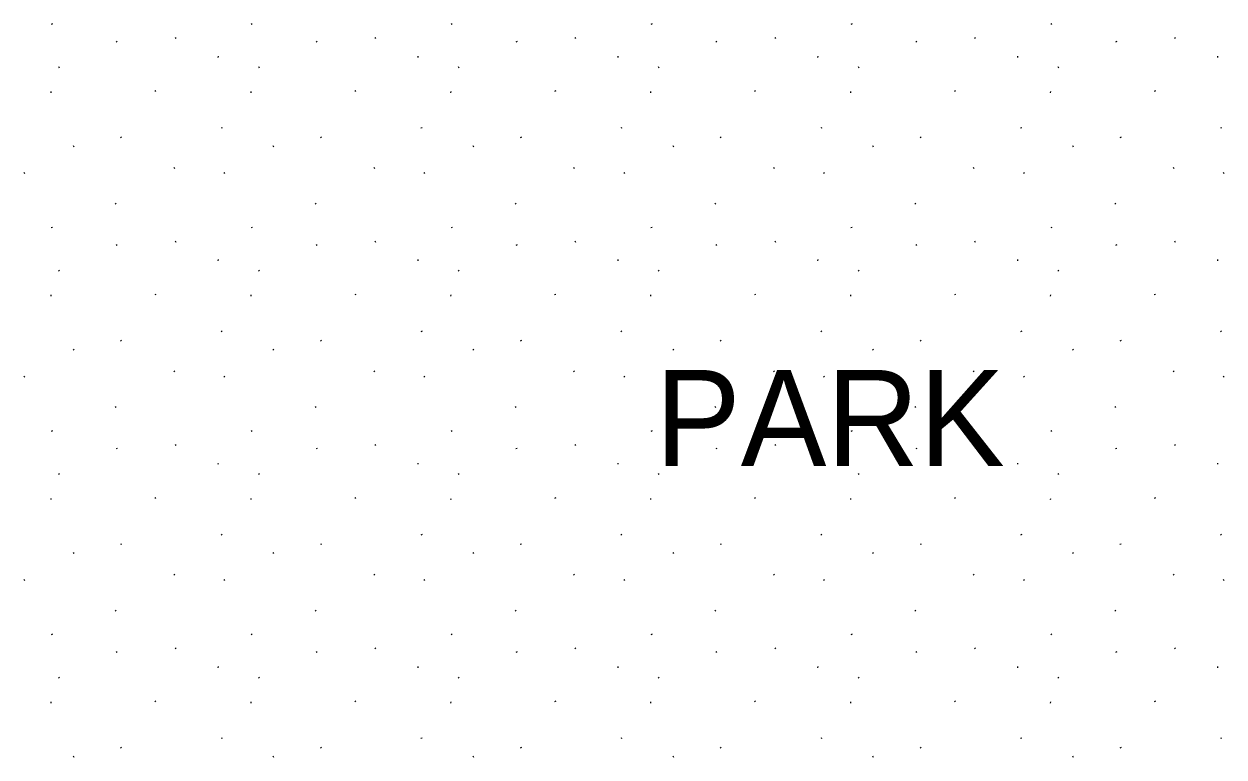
# Model space of a CAD drawing. Extents: x 419396 to 421519, y 4453567 to 4456767.
# Drawn here: x 420346 to 420396, y 4454755.4 to 4454786 of the extents above; entities that cross this region are included whole.
import ezdxf

# ---------------------------------------------------------------- set-up
doc = ezdxf.new("R2010")
doc.units = 0
doc.layers.add('Level 41', color=7, linetype='Continuous')
doc.layers.add('LEVEL61', color=7, linetype='Continuous')

msp = doc.modelspace()

# ---------------------------------------------------------------- linework, layer by layer
at = {"layer": 'Level 41'}
for p, q in [((420347.213, 4454785.976), (420347.166, 4454785.953)), ((420355.545, 4454785.976), (420355.499, 4454785.953)), ((420363.878, 4454785.976), (420363.831, 4454785.953)), ((420372.21, 4454785.976), (420372.163, 4454785.953)), ((420380.542, 4454785.976), (420380.495, 4454785.953)), ((420388.874, 4454785.976), (420388.827, 4454785.953)), ((420352.325, 4454785.411), (420352.353, 4454785.367)), ((420360.657, 4454785.411), (420360.685, 4454785.367)), ((420368.989, 4454785.411), (420369.017, 4454785.367)), ((420377.321, 4454785.411), (420377.349, 4454785.367)), ((420385.654, 4454785.411), (420385.682, 4454785.367)), ((420393.986, 4454785.411), (420394.014, 4454785.367)), ((420349.916, 4454785.247), (420349.869, 4454785.224)), ((420358.248, 4454785.247), (420358.202, 4454785.224)), ((420366.581, 4454785.247), (420366.534, 4454785.224)), ((420374.913, 4454785.247), (420374.866, 4454785.224)), ((420383.245, 4454785.247), (420383.198, 4454785.224)), ((420391.577, 4454785.247), (420391.53, 4454785.224)), ((420354.124, 4454784.582), (420354.132, 4454784.633)), ((420362.457, 4454784.582), (420362.464, 4454784.633)), ((420370.789, 4454784.582), (420370.796, 4454784.633)), ((420379.121, 4454784.582), (420379.128, 4454784.633)), ((420387.453, 4454784.582), (420387.461, 4454784.633)), ((420395.785, 4454784.582), (420395.793, 4454784.633)), ((420347.466, 4454784.196), (420347.494, 4454784.152)), ((420355.798, 4454784.196), (420355.826, 4454784.152)), ((420364.13, 4454784.196), (420364.158, 4454784.152)), ((420372.462, 4454784.196), (420372.49, 4454784.152)), ((420380.794, 4454784.196), (420380.822, 4454784.152)), ((420389.127, 4454784.196), (420389.155, 4454784.152)), ((420347.159, 4454783.108), (420347.166, 4454783.159)), ((420351.526, 4454783.182), (420351.479, 4454783.159)), ((420355.491, 4454783.108), (420355.499, 4454783.159)), ((420359.858, 4454783.182), (420359.811, 4454783.159)), ((420363.823, 4454783.108), (420363.831, 4454783.159)), ((420368.19, 4454783.182), (420368.143, 4454783.159)), ((420372.155, 4454783.108), (420372.163, 4454783.159)), ((420376.522, 4454783.182), (420376.476, 4454783.159)), ((420380.488, 4454783.108), (420380.495, 4454783.159)), ((420384.855, 4454783.182), (420384.808, 4454783.159)), ((420388.82, 4454783.108), (420388.827, 4454783.159)), ((420393.187, 4454783.182), (420393.14, 4454783.159)), ((420354.289, 4454781.648), (420354.243, 4454781.625)), ((420362.622, 4454781.648), (420362.575, 4454781.625)), ((420370.954, 4454781.648), (420370.907, 4454781.625)), ((420379.286, 4454781.648), (420379.239, 4454781.625)), ((420387.618, 4454781.648), (420387.571, 4454781.625)), ((420395.95, 4454781.648), (420395.904, 4454781.625)), ((420348.073, 4454780.9), (420348.101, 4454780.857)), ((420350.098, 4454781.253), (420350.052, 4454781.23)), ((420356.405, 4454780.9), (420356.433, 4454780.857)), ((420358.431, 4454781.253), (420358.384, 4454781.23)), ((420364.737, 4454780.9), (420364.765, 4454780.857)), ((420366.763, 4454781.253), (420366.716, 4454781.23)), ((420373.069, 4454780.9), (420373.098, 4454780.857)), ((420375.095, 4454781.253), (420375.048, 4454781.23)), ((420381.402, 4454780.9), (420381.43, 4454780.857)), ((420383.427, 4454781.253), (420383.38, 4454781.23)), ((420389.734, 4454780.9), (420389.762, 4454780.857)), ((420391.759, 4454781.253), (420391.713, 4454781.23)), ((420352.27, 4454779.997), (420352.298, 4454779.953)), ((420360.603, 4454779.997), (420360.631, 4454779.953)), ((420368.935, 4454779.997), (420368.963, 4454779.953)), ((420377.267, 4454779.997), (420377.295, 4454779.953)), ((420385.599, 4454779.997), (420385.627, 4454779.953)), ((420393.931, 4454779.997), (420393.959, 4454779.953)), ((420346.027, 4454779.777), (420346.055, 4454779.733)), ((420354.359, 4454779.777), (420354.388, 4454779.733)), ((420362.692, 4454779.777), (420362.72, 4454779.733)), ((420371.024, 4454779.777), (420371.052, 4454779.733)), ((420379.356, 4454779.777), (420379.384, 4454779.733)), ((420387.688, 4454779.777), (420387.716, 4454779.733)), ((420396.02, 4454779.777), (420396.049, 4454779.733)), ((420349.834, 4454778.501), (420349.862, 4454778.457)), ((420358.167, 4454778.501), (420358.195, 4454778.457)), ((420366.499, 4454778.501), (420366.527, 4454778.457)), ((420374.831, 4454778.501), (420374.859, 4454778.457)), ((420383.163, 4454778.501), (420383.191, 4454778.457)), ((420391.495, 4454778.501), (420391.523, 4454778.457)), ((420347.213, 4454777.488), (420347.166, 4454777.465)), ((420355.545, 4454777.488), (420355.499, 4454777.465)), ((420363.878, 4454777.488), (420363.831, 4454777.465)), ((420372.21, 4454777.488), (420372.163, 4454777.465)), ((420380.542, 4454777.488), (420380.495, 4454777.465)), ((420388.874, 4454777.488), (420388.827, 4454777.465)), ((420352.325, 4454776.922), (420352.353, 4454776.878)), ((420360.657, 4454776.922), (420360.685, 4454776.878)), ((420368.989, 4454776.922), (420369.017, 4454776.878)), ((420377.321, 4454776.922), (420377.349, 4454776.878)), ((420385.654, 4454776.922), (420385.682, 4454776.878)), ((420393.986, 4454776.922), (420394.014, 4454776.878)), ((420349.916, 4454776.759), (420349.869, 4454776.736)), ((420358.248, 4454776.759), (420358.202, 4454776.736)), ((420366.581, 4454776.759), (420366.534, 4454776.736)), ((420374.913, 4454776.759), (420374.866, 4454776.736)), ((420383.245, 4454776.759), (420383.198, 4454776.736)), ((420391.577, 4454776.759), (420391.53, 4454776.736)), ((420354.124, 4454776.093), (420354.132, 4454776.144)), ((420362.457, 4454776.093), (420362.464, 4454776.144)), ((420370.789, 4454776.093), (420370.796, 4454776.144)), ((420379.121, 4454776.093), (420379.128, 4454776.144)), ((420387.453, 4454776.093), (420387.461, 4454776.144)), ((420395.785, 4454776.093), (420395.793, 4454776.144)), ((420347.466, 4454775.707), (420347.494, 4454775.663)), ((420355.798, 4454775.707), (420355.826, 4454775.663)), ((420364.13, 4454775.707), (420364.158, 4454775.663)), ((420372.462, 4454775.707), (420372.49, 4454775.663)), ((420380.794, 4454775.707), (420380.822, 4454775.663)), ((420389.127, 4454775.707), (420389.155, 4454775.663)), ((420347.159, 4454774.619), (420347.166, 4454774.671)), ((420351.526, 4454774.694), (420351.479, 4454774.671)), ((420355.491, 4454774.619), (420355.499, 4454774.671)), ((420359.858, 4454774.694), (420359.811, 4454774.671)), ((420363.823, 4454774.619), (420363.831, 4454774.671)), ((420368.19, 4454774.694), (420368.143, 4454774.671)), ((420372.155, 4454774.619), (420372.163, 4454774.671)), ((420376.522, 4454774.694), (420376.476, 4454774.671)), ((420380.488, 4454774.619), (420380.495, 4454774.671)), ((420384.855, 4454774.694), (420384.808, 4454774.671)), ((420388.82, 4454774.619), (420388.827, 4454774.671)), ((420393.187, 4454774.694), (420393.14, 4454774.671)), ((420354.289, 4454773.159), (420354.243, 4454773.137)), ((420362.622, 4454773.159), (420362.575, 4454773.137)), ((420370.954, 4454773.159), (420370.907, 4454773.137)), ((420379.286, 4454773.159), (420379.239, 4454773.137)), ((420387.618, 4454773.159), (420387.571, 4454773.137)), ((420395.95, 4454773.159), (420395.904, 4454773.137)), ((420348.073, 4454772.412), (420348.101, 4454772.368)), ((420350.098, 4454772.764), (420350.052, 4454772.742)), ((420356.405, 4454772.412), (420356.433, 4454772.368)), ((420358.431, 4454772.764), (420358.384, 4454772.742)), ((420364.737, 4454772.412), (420364.765, 4454772.368)), ((420366.763, 4454772.764), (420366.716, 4454772.742)), ((420373.069, 4454772.412), (420373.098, 4454772.368)), ((420375.095, 4454772.764), (420375.048, 4454772.742)), ((420381.402, 4454772.412), (420381.43, 4454772.368)), ((420383.427, 4454772.764), (420383.38, 4454772.742)), ((420389.734, 4454772.412), (420389.762, 4454772.368)), ((420391.759, 4454772.764), (420391.713, 4454772.742)), ((420352.27, 4454771.508), (420352.298, 4454771.465)), ((420360.603, 4454771.508), (420360.631, 4454771.465)), ((420368.935, 4454771.508), (420368.963, 4454771.465)), ((420377.267, 4454771.508), (420377.295, 4454771.465)), ((420385.599, 4454771.508), (420385.627, 4454771.465)), ((420393.931, 4454771.508), (420393.959, 4454771.465)), ((420346.027, 4454771.288), (420346.055, 4454771.244)), ((420354.359, 4454771.288), (420354.388, 4454771.244)), ((420362.692, 4454771.288), (420362.72, 4454771.244)), ((420371.024, 4454771.288), (420371.052, 4454771.244)), ((420379.356, 4454771.288), (420379.384, 4454771.244)), ((420387.688, 4454771.288), (420387.716, 4454771.244)), ((420396.02, 4454771.288), (420396.049, 4454771.244)), ((420349.834, 4454770.012), (420349.862, 4454769.969)), ((420358.167, 4454770.012), (420358.195, 4454769.969)), ((420366.499, 4454770.012), (420366.527, 4454769.969)), ((420374.831, 4454770.012), (420374.859, 4454769.969)), ((420383.163, 4454770.012), (420383.191, 4454769.969)), ((420391.495, 4454770.012), (420391.523, 4454769.969)), ((420347.213, 4454768.999), (420347.166, 4454768.976)), ((420355.545, 4454768.999), (420355.499, 4454768.976)), ((420363.878, 4454768.999), (420363.831, 4454768.976)), ((420372.21, 4454768.999), (420372.163, 4454768.976)), ((420380.542, 4454768.999), (420380.495, 4454768.976)), ((420388.874, 4454768.999), (420388.827, 4454768.976)), ((420352.325, 4454768.433), (420352.353, 4454768.389)), ((420360.657, 4454768.433), (420360.685, 4454768.389)), ((420368.989, 4454768.433), (420369.017, 4454768.389)), ((420377.321, 4454768.433), (420377.349, 4454768.389)), ((420385.654, 4454768.433), (420385.682, 4454768.389)), ((420393.986, 4454768.433), (420394.014, 4454768.389)), ((420349.916, 4454768.27), (420349.869, 4454768.247)), ((420358.248, 4454768.27), (420358.202, 4454768.247)), ((420366.581, 4454768.27), (420366.534, 4454768.247)), ((420374.913, 4454768.27), (420374.866, 4454768.247)), ((420383.245, 4454768.27), (420383.198, 4454768.247)), ((420391.577, 4454768.27), (420391.53, 4454768.247)), ((420354.124, 4454767.604), (420354.132, 4454767.655)), ((420362.457, 4454767.604), (420362.464, 4454767.655)), ((420370.789, 4454767.604), (420370.796, 4454767.655)), ((420379.121, 4454767.604), (420379.128, 4454767.655)), ((420387.453, 4454767.604), (420387.461, 4454767.655)), ((420395.785, 4454767.604), (420395.793, 4454767.655)), ((420347.466, 4454767.218), (420347.494, 4454767.175)), ((420355.798, 4454767.218), (420355.826, 4454767.175)), ((420364.13, 4454767.218), (420364.158, 4454767.175)), ((420372.462, 4454767.218), (420372.49, 4454767.175)), ((420380.794, 4454767.218), (420380.822, 4454767.175)), ((420389.127, 4454767.218), (420389.155, 4454767.175)), ((420347.159, 4454766.131), (420347.166, 4454766.182)), ((420351.526, 4454766.205), (420351.479, 4454766.182)), ((420355.491, 4454766.131), (420355.499, 4454766.182)), ((420359.858, 4454766.205), (420359.811, 4454766.182)), ((420363.823, 4454766.131), (420363.831, 4454766.182)), ((420368.19, 4454766.205), (420368.143, 4454766.182)), ((420372.155, 4454766.131), (420372.163, 4454766.182)), ((420376.522, 4454766.205), (420376.476, 4454766.182)), ((420380.488, 4454766.131), (420380.495, 4454766.182)), ((420384.855, 4454766.205), (420384.808, 4454766.182)), ((420388.82, 4454766.131), (420388.827, 4454766.182)), ((420393.187, 4454766.205), (420393.14, 4454766.182)), ((420354.289, 4454764.671), (420354.243, 4454764.648)), ((420362.622, 4454764.671), (420362.575, 4454764.648)), ((420370.954, 4454764.671), (420370.907, 4454764.648)), ((420379.286, 4454764.671), (420379.239, 4454764.648)), ((420387.618, 4454764.671), (420387.571, 4454764.648)), ((420395.95, 4454764.671), (420395.904, 4454764.648)), ((420348.073, 4454763.923), (420348.101, 4454763.879)), ((420350.098, 4454764.276), (420350.052, 4454764.253)), ((420356.405, 4454763.923), (420356.433, 4454763.879)), ((420358.431, 4454764.276), (420358.384, 4454764.253)), ((420364.737, 4454763.923), (420364.765, 4454763.879)), ((420366.763, 4454764.276), (420366.716, 4454764.253)), ((420373.069, 4454763.923), (420373.098, 4454763.879)), ((420375.095, 4454764.276), (420375.048, 4454764.253)), ((420381.402, 4454763.923), (420381.43, 4454763.879)), ((420383.427, 4454764.276), (420383.38, 4454764.253)), ((420389.734, 4454763.923), (420389.762, 4454763.879)), ((420391.759, 4454764.276), (420391.713, 4454764.253)), ((420352.27, 4454763.019), (420352.298, 4454762.976)), ((420360.603, 4454763.019), (420360.631, 4454762.976)), ((420368.935, 4454763.019), (420368.963, 4454762.976)), ((420377.267, 4454763.019), (420377.295, 4454762.976)), ((420385.599, 4454763.019), (420385.627, 4454762.976)), ((420393.931, 4454763.019), (420393.959, 4454762.976)), ((420346.027, 4454762.799), (420346.055, 4454762.755)), ((420354.359, 4454762.799), (420354.388, 4454762.755)), ((420362.692, 4454762.799), (420362.72, 4454762.755)), ((420371.024, 4454762.799), (420371.052, 4454762.755)), ((420379.356, 4454762.799), (420379.384, 4454762.755)), ((420387.688, 4454762.799), (420387.716, 4454762.755)), ((420396.02, 4454762.799), (420396.049, 4454762.755)), ((420349.834, 4454761.523), (420349.862, 4454761.48)), ((420358.167, 4454761.523), (420358.195, 4454761.48)), ((420366.499, 4454761.523), (420366.527, 4454761.48)), ((420374.831, 4454761.523), (420374.859, 4454761.48)), ((420383.163, 4454761.523), (420383.191, 4454761.48)), ((420391.495, 4454761.523), (420391.523, 4454761.48)), ((420347.213, 4454760.51), (420347.166, 4454760.487)), ((420355.545, 4454760.51), (420355.499, 4454760.487)), ((420363.878, 4454760.51), (420363.831, 4454760.487)), ((420372.21, 4454760.51), (420372.163, 4454760.487)), ((420380.542, 4454760.51), (420380.495, 4454760.487)), ((420388.874, 4454760.51), (420388.827, 4454760.487)), ((420352.325, 4454759.944), (420352.353, 4454759.901)), ((420360.657, 4454759.944), (420360.685, 4454759.901)), ((420368.989, 4454759.944), (420369.017, 4454759.901)), ((420377.321, 4454759.944), (420377.349, 4454759.901)), ((420385.654, 4454759.944), (420385.682, 4454759.901)), ((420393.986, 4454759.944), (420394.014, 4454759.901)), ((420349.916, 4454759.781), (420349.869, 4454759.758)), ((420358.248, 4454759.781), (420358.202, 4454759.758)), ((420366.581, 4454759.781), (420366.534, 4454759.758)), ((420374.913, 4454759.781), (420374.866, 4454759.758)), ((420383.245, 4454759.781), (420383.198, 4454759.758)), ((420391.577, 4454759.781), (420391.53, 4454759.758)), ((420354.124, 4454759.115), (420354.132, 4454759.166)), ((420362.457, 4454759.115), (420362.464, 4454759.166)), ((420370.789, 4454759.115), (420370.796, 4454759.166)), ((420379.121, 4454759.115), (420379.128, 4454759.166)), ((420387.453, 4454759.115), (420387.461, 4454759.166)), ((420395.785, 4454759.115), (420395.793, 4454759.166)), ((420347.466, 4454758.729), (420347.494, 4454758.686)), ((420355.798, 4454758.729), (420355.826, 4454758.686)), ((420364.13, 4454758.729), (420364.158, 4454758.686)), ((420372.462, 4454758.729), (420372.49, 4454758.686)), ((420380.794, 4454758.729), (420380.822, 4454758.686)), ((420389.127, 4454758.729), (420389.155, 4454758.686)), ((420347.159, 4454757.642), (420347.166, 4454757.693)), ((420351.526, 4454757.716), (420351.479, 4454757.693)), ((420355.491, 4454757.642), (420355.499, 4454757.693)), ((420359.858, 4454757.716), (420359.811, 4454757.693)), ((420363.823, 4454757.642), (420363.831, 4454757.693)), ((420368.19, 4454757.716), (420368.143, 4454757.693)), ((420372.155, 4454757.642), (420372.163, 4454757.693)), ((420376.522, 4454757.716), (420376.476, 4454757.693)), ((420380.488, 4454757.642), (420380.495, 4454757.693)), ((420384.855, 4454757.716), (420384.808, 4454757.693)), ((420388.82, 4454757.642), (420388.827, 4454757.693)), ((420393.187, 4454757.716), (420393.14, 4454757.693)), ((420354.289, 4454756.182), (420354.243, 4454756.159)), ((420362.622, 4454756.182), (420362.575, 4454756.159)), ((420370.954, 4454756.182), (420370.907, 4454756.159)), ((420379.286, 4454756.182), (420379.239, 4454756.159)), ((420387.618, 4454756.182), (420387.571, 4454756.159)), ((420395.95, 4454756.182), (420395.904, 4454756.159)), ((420348.073, 4454755.434), (420348.101, 4454755.39)), ((420350.098, 4454755.787), (420350.052, 4454755.764)), ((420356.405, 4454755.434), (420356.433, 4454755.39)), ((420358.431, 4454755.787), (420358.384, 4454755.764)), ((420364.737, 4454755.434), (420364.765, 4454755.39)), ((420366.763, 4454755.787), (420366.716, 4454755.764)), ((420373.069, 4454755.434), (420373.098, 4454755.39)), ((420375.095, 4454755.787), (420375.048, 4454755.764)), ((420381.402, 4454755.434), (420381.43, 4454755.39)), ((420383.427, 4454755.787), (420383.38, 4454755.764)), ((420389.734, 4454755.434), (420389.762, 4454755.39)), ((420391.759, 4454755.787), (420391.713, 4454755.764))]:
    msp.add_line(p, q, dxfattribs=at)

# ---------------------------------------------------------------- texts
at = {"layer": 'LEVEL61'}
msp.add_text('PARK', height=4, dxfattribs=at).set_placement((420372.339, 4454767.537))

doc.saveas('drawing.dxf')
